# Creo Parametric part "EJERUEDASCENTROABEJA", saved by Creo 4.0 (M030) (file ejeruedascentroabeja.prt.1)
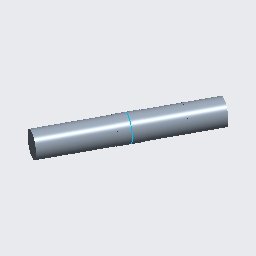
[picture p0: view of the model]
Units: millimeter Newton Second (mmNs); MM, TONNE, SECS

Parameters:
  MODELED_BY = "AJ"

Created from: MMNS_PART_SOLID.PRT

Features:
  1. datum plane "RIGHT"
  2. datum plane "TOP"
  3. datum plane "FRONT"
  4. coordinate system
  5. extrusion "Extrude 1"
  6. datum plane "DTM1"
  7. extrusion "Extrude 2"
  8. datum plane "DTM2"
  9. sketch "Sketch 1"
  10. sketch "Sketch 1 (2)"
  11. extrusion "Extrude 3"
  12. mirror "Mirror 1"
  13. extrusion "Extrude 3 (2)"

Surfaces: 8 plane, 4 cylinder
